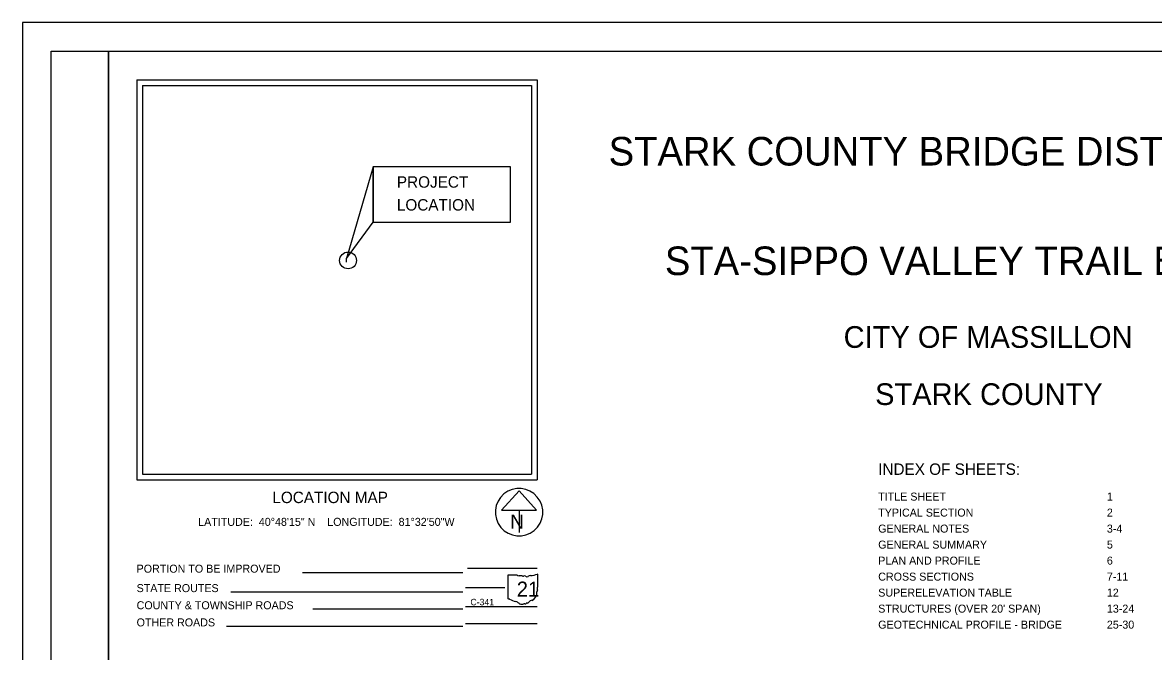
# Model space of a CAD drawing. Extents: x 0 to 34, y 0 to 22.
# Drawn here: x 0 to 19.78, y 11 to 22 of the extents above; entities that cross this region are included whole.
import ezdxf

# ---------------------------------------------------------------- set-up
doc = ezdxf.new("R2010")
doc.units = 0
for name, color, linetype in [('Default', 7, 'Continuous'), ('GM_X_Adjacent_County', 7, 'Continuous'), ('GM_X_County', 7, 'Continuous'), ('GM_X_Section', 7, 'Continuous'), ('GM_X_Township', 7, 'Continuous')]:
    doc.layers.add(name, color=color, linetype=linetype)

msp = doc.modelspace()

# ---------------------------------------------------------------- linework, layer by layer
at = {"layer": 'Default'}
for p, q in [((8.487, 12.329), (8.487, 11.929)), ((8.647, 12.336), (8.492, 12.336)), ((9.015, 12.137), (9.015, 12.346)), ((9.015, 12.137), (9.015, 12.137))]:
    msp.add_line(p, q, dxfattribs=at)
for centre, radius, start, end in [((8.493, 12.33), 0.00611, 98.1301, 188.1301), ((8.684, 12.383), 0.0593, 231.6195, 271.1119), ((8.703, 12.111), 0.213, 80.4867, 94.9883), ((8.752, 12.332), 0.0171, 219.7921, 297.1024), ((8.777, 12.286), 0.0355, 54.4667, 119.1411), ((8.823, 12.349), 0.0428, 233.8562, 294.8282), ((8.898, 12.214), 0.113, 97.3462, 120.7689), ((8.827, 12.882), 0.559, 275.8445, 288.9065), ((9.009, 12.347), 0.00587, 351.8621, 97.738), ((9.036, 12.049), 0.0397, 136.8065, 186.9296), ((9.013, 12.121), 0.00909, 107.944, 210.337), ((8.955, 12.095), 0.0545, 340.033, 23.6496), ((9.008, 12.136), 0.00628, 289.6038, 7.7341), ((8.493, 11.928), 0.00616, 171.9584, 258.3066), ((8.494, 11.969), 0.047, 267.339, 280.6039), ((8.504, 11.906), 0.017, 29.7484, 93.2717), ((8.718, 12.265), 0.404, 240.4129, 257.1985), ((8.598, 11.749), 0.126, 47.1842, 75.836), ((8.917, 11.817), 0.0766, 94.4031, 142.5768), ((8.858, 12.022), 0.14, 292.3089, 8.9858), ((8.734, 11.904), 0.0802, 230.7004, 286.2918), ((8.781, 11.765), 0.0659, 85.6951, 111.2099), ((8.786, 11.874), 0.0427, 268.777, 315.5493), ((8.825, 11.835), 0.012, 65.7517, 132.6484), ((8.82, 11.89), 0.0452, 282.8732, 323.2771)]:
    msp.add_arc(centre, radius, start, end, dxfattribs=at)
at = {"layer": 'GM_X_Adjacent_County'}
msp.add_line((5.668, 17.81), (5.665, 17.872), dxfattribs=at)
msp.add_lwpolyline([(6.132, 19.475), (6.132, 18.511), (8.535, 18.511), (8.535, 19.475), (6.132, 19.475)], dxfattribs=at)
msp.add_circle((5.693, 17.84), 0.147, dxfattribs=at)
at = {"layer": 'GM_X_County'}
for points in [[(0.5, 21.5), (1.5, 21.5), (1.5, 0.5), (0.5, 0.5)], [(1.5, 21.5), (33.5, 21.5), (33.5, 0.5), (1.5, 0.5)]]:
    msp.add_lwpolyline(points, close=True, dxfattribs=at)
at = {"layer": 'GM_X_Section'}
msp.add_lwpolyline([(0, 0), (34, 0), (34, 22), (0, 22)], close=True, dxfattribs=at)
at = {"layer": 'GM_X_Township'}
for p, q in [((2, 21), (9, 21)), ((2, 21), (2, 14)), ((9, 21), (9, 14)), ((2.1, 20.9), (2.1, 14.1)), ((2.1, 20.9), (8.9, 20.9)), ((8.9, 20.9), (8.9, 14.1)), ((2.1, 14.1), (8.9, 14.1)), ((2, 14), (9, 14)), ((8.685, 13.809), (8.377, 13.468)), ((8.992, 13.468), (8.685, 13.809)), ((8.377, 13.468), (8.992, 13.468)), ((8.685, 13.468), (8.685, 13.081)), ((8.685, 13.435), (8.685, 13.435)), ((8.685, 13.435), (8.685, 13.435)), ((7.7, 12.377), (4.894, 12.377)), ((7.783, 12.455), (9, 12.455)), ((8.435, 12.109), (7.75, 12.109)), ((7.7, 12.037), (3.645, 12.037)), ((7.7, 11.737), (5.078, 11.737)), ((9, 11.782), (7.75, 11.782)), ((9, 11.482), (7.75, 11.482)), ((7.7, 11.437), (3.566, 11.437))]:
    msp.add_line(p, q, dxfattribs=at)
msp.add_lwpolyline([(6.132, 18.511), (6.132, 19.475), (5.665, 17.872)], close=True, dxfattribs=at)
msp.add_arc((8.685, 13.435), 0.415, 129.7798, 129.7633, dxfattribs=at)

# ---------------------------------------------------------------- texts
at = {"layer": 'Default'}
msp.add_text('21', height=0.2637, dxfattribs=at).set_placement((8.644, 11.957))
msp.add_text('C-341', height=0.1136, rotation=359.857, dxfattribs=at).set_placement((7.833, 11.806))
at = {"layer": 'GM_X_Adjacent_County'}
for s, height, p in [('STARK COUNTY BRIDGE DISTRICT', 0.5, (10.251, 19.5)), ('STA-SIPPO VALLEY TRAIL BRIDGE 8', 0.5, (11.235, 17.583)), ('CITY OF MASSILLON', 0.38, (14.362, 16.31)), ('STARK COUNTY', 0.38, (14.913, 15.31)), ('INDEX OF SHEETS:', 0.2, (14.967, 14.088)), ('LOCATION MAP', 0.2, (4.369, 13.594)), ('TITLE SHEET', 0.14, (14.967, 13.638)), ('1', 0.14, (18.967, 13.638)), ('TYPICAL SECTION', 0.14, (14.967, 13.358)), ('2', 0.14, (18.967, 13.358)), ('LATITUDE:  40°48\'15" N    LONGITUDE:  81°32\'50"W', 0.14, (3.071, 13.196)), ('GENERAL NOTES', 0.14, (14.967, 13.078)), ('3-4', 0.14, (18.967, 13.078)), ('GENERAL SUMMARY', 0.14, (14.967, 12.798)), ('5', 0.14, (18.967, 12.798)), ('PLAN AND PROFILE', 0.14, (14.967, 12.518)), ('6', 0.14, (18.967, 12.518)), ('PORTION TO BE IMPROVED', 0.14, (1.994, 12.377)), ('CROSS SECTIONS', 0.14, (14.967, 12.238)), ('7-11', 0.14, (18.967, 12.238)), ('STATE ROUTES', 0.14, (1.994, 12.037)), ('SUPERELEVATION TABLE', 0.14, (14.967, 11.958)), ('12', 0.14, (18.967, 11.958)), ('COUNTY & TOWNSHIP ROADS', 0.14, (1.994, 11.737)), ("STRUCTURES (OVER 20' SPAN)", 0.14, (14.967, 11.678)), ('13-24', 0.14, (18.967, 11.678)), ('OTHER ROADS', 0.14, (1.994, 11.437)), ('GEOTECHNICAL PROFILE - BRIDGE ', 0.14, (14.967, 11.398)), ('25-30', 0.14, (18.967, 11.398))]:
    msp.add_text(s, height=height, dxfattribs=at).set_placement(p)
at = {"layer": 'GM_X_Township'}
for s, height, p in [('PROJECT ', 0.2, (6.547, 19.112)), ('LOCATION', 0.2, (6.547, 18.712)), ('N', 0.25, (8.529, 13.144))]:
    msp.add_text(s, height=height, dxfattribs=at).set_placement(p)

doc.saveas('drawing.dxf')
